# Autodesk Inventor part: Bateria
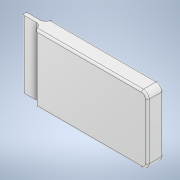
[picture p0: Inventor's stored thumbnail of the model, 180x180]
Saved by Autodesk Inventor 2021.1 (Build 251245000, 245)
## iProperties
Created: 2021-06
Part Number: Bateria
Material: Genérico
Document SubType Name: Modeling
Designer: Ricardo
Density: 1 g/cm^3
Appearance: Valor por defecto
Author: Ricardo
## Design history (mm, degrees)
sketch "Boceto1"
  geometry: L1 (-34, 17.5)-(34, 17.5); L2 (34, 17.5)-(34, -17.5); L3 (34, -17.5)-(-34, -17.5); L4 (-34, -17.5)-(-34, 17.5); L5 (-34, 17.5)-(34, -17.5); L6 (34, 17.5)-(-34, -17.5); L7 (-34, 17.5)-(-34, -17.5); L8 (-34, -17.5)-(-24, -17.5); L9 (-24, -17.5)-(-24, 17.5); L10 (-24, 17.5)-(-34, 17.5); 3 further points
  constraints: 20 end point, 4 parallel, 3 perpendicular, 2 midpoint, 1 horizontal
  dimensions: "d0" = 68 distance of L2.end L3.end; "d1" = 35 distance of L1.end L2.end; "d5" = 10 distance of L8.end L3.end
extrude "Extrusión1" new body sketch "Boceto1" stored distance "d2" = 8.5; taper "d3" = 0 deg
extrude "Extrusión2" join sketch "Boceto1" stored distance "d6" = 2; taper "d7" = 0 deg
fillet "Empalme2" dims "d8" = 3
fillet "Empalme3" dims "d9" = 3, "d10" = 1
node "Sólido1"
